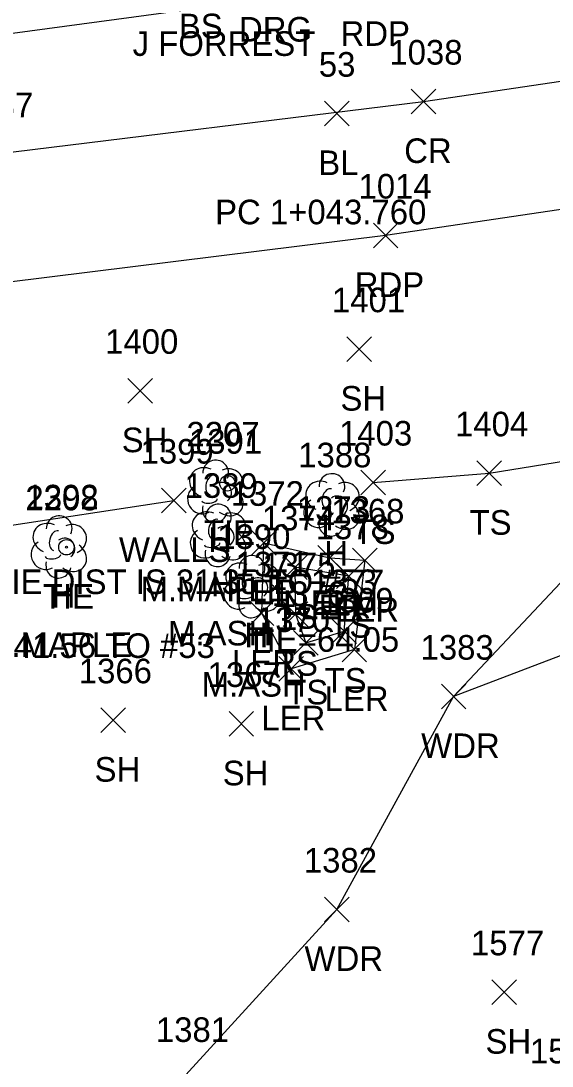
# Model space of a CAD drawing. Extents: x 1526508 to 1531550, y 369926 to 373082.
# Drawn here: x 1530976.9 to 1531020.1, y 370058.1 to 370143.1 of the extents above; entities that cross this region are included whole.
import ezdxf

# ---------------------------------------------------------------- set-up
doc = ezdxf.new("R2010")
doc.units = 0
for name, color, linetype in [('C_A', 7, 'Continuous'), ('C_C', 7, 'Continuous'), ('C_I', 7, 'Continuous'), ('C_TIC', 7, 'Continuous'), ('CBP', 7, 'Continuous'), ('L_A', 7, 'Continuous'), ('L_C', 7, 'Continuous'), ('L_I', 7, 'Continuous'), ('L_TIC', 7, 'Continuous'), ('LARO', 7, 'Continuous'), ('LAWA', 7, 'Continuous'), ('LELB', 7, 'Continuous'), ('LTD', 7, 'Continuous'), ('LWS', 7, 'Continuous'), ('P_A', 7, 'Continuous'), ('P_I', 7, 'Continuous'), ('P_TIC', 7, 'Continuous'), ('PET', 7, 'Continuous'), ('PRC', 7, 'Continuous'), ('R_A', 7, 'Continuous')]:
    doc.layers.add(name, color=color, linetype=linetype)

msp = doc.modelspace()

# ---------------------------------------------------------------- linework, layer by layer
at = {"layer": 'C_TIC'}
for points in [[(1531001.631, 370134.575), (1531003.631, 370136.575)], [(1531003.631, 370134.575), (1531001.631, 370136.575)]]:
    msp.add_lwpolyline(points, dxfattribs=at)
at = {"layer": 'CBP'}
for centre, radius in [((1530993.737, 370105.51), 0.625), ((1530993.737, 370105.51), 0.0833), ((1530980.642, 370100.315), 0.625), ((1530980.642, 370100.315), 0.0833)]:
    msp.add_circle(centre, radius, dxfattribs=at)
at = {"layer": 'L_TIC'}
for points in [[(1531003.438, 370115.426), (1531005.438, 370117.426)], [(1531005.438, 370115.426), (1531003.438, 370117.426)], [(1530985.649, 370112.044), (1530987.649, 370114.044)], [(1530987.649, 370112.044), (1530985.649, 370114.044)], [(1531014.011, 370105.334), (1531016.011, 370107.334)], [(1531016.011, 370105.334), (1531014.011, 370107.334)], [(1531004.583, 370104.584), (1531006.583, 370106.584)], [(1531006.583, 370104.584), (1531004.583, 370106.584)], [(1530988.373, 370103.119), (1530990.373, 370105.119)], [(1530990.373, 370103.119), (1530988.373, 370105.119)], [(1530995.695, 370099.685), (1530997.695, 370101.685)], [(1530997.695, 370099.685), (1530995.695, 370101.685)], [(1531001.073, 370098.469), (1531003.073, 370100.469)], [(1531003.073, 370098.469), (1531001.073, 370100.469)], [(1531003.914, 370098.255), (1531005.914, 370100.255)], [(1531005.914, 370098.255), (1531003.914, 370100.255)], [(1530998.226, 370097.686), (1531000.226, 370099.686)], [(1531000.226, 370097.686), (1530998.226, 370099.686)], [(1531002.604, 370096.968), (1531004.604, 370098.968)], [(1531004.604, 370096.968), (1531002.604, 370098.968)], [(1530995.521, 370093.953), (1530997.521, 370095.953)], [(1530997.521, 370093.953), (1530995.521, 370095.953)], [(1530998.264, 370093.874), (1531000.264, 370095.874)], [(1531000.264, 370093.874), (1530998.264, 370095.874)], [(1531002.222, 370092.494), (1531004.222, 370094.494)], [(1531004.222, 370092.494), (1531002.222, 370094.494)], [(1530999.105, 370091.539), (1531001.105, 370093.539)], [(1531001.105, 370091.539), (1530999.105, 370093.539)], [(1531003.055, 370091.009), (1531005.055, 370093.009)], [(1531005.055, 370091.009), (1531003.055, 370093.009)], [(1530997.909, 370089.427), (1530999.909, 370091.427)], [(1530999.909, 370089.427), (1530997.909, 370091.427)], [(1531011.129, 370087.176), (1531013.129, 370089.176)], [(1531013.129, 370087.176), (1531011.129, 370089.176)], [(1530983.443, 370085.256), (1530985.443, 370087.256)], [(1530985.443, 370085.256), (1530983.443, 370087.256)], [(1530993.867, 370084.959), (1530995.867, 370086.959)], [(1530995.867, 370084.959), (1530993.867, 370086.959)], [(1531001.64, 370069.867), (1531003.64, 370071.867)], [(1531003.64, 370069.867), (1531001.64, 370071.867)], [(1531015.232, 370063.138), (1531017.232, 370065.138)], [(1531017.232, 370063.138), (1531015.232, 370065.138)]]:
    msp.add_lwpolyline(points, dxfattribs=at)
at = {"layer": 'LARO'}
for points in [[(1531004.914, 370099.255), (1531004.055, 370092.009), (1530998.909, 370090.427), (1530996.521, 370094.953), (1530996.695, 370100.685), (1531002.073, 370099.469)], [(1531002.073, 370099.469), (1531004.914, 370099.255)]]:
    msp.add_lwpolyline(points, dxfattribs=at)
at = {"layer": 'LAWA'}
msp.add_lwpolyline([(1530968.161, 370037.392), (1530979.881, 370048.994), (1530990.042, 370057.094), (1531002.64, 370070.867), (1531012.129, 370088.176), (1531024.743, 370101.609), (1531031.255, 370108.889), (1531038.675, 370107.681), (1531051.109, 370105.813), (1531063.824, 370101.61), (1531080.52, 370097.978), (1531114.388, 370088.681)], dxfattribs=at)
at = {"layer": 'LELB'}
for points in [[(1531005.583, 370105.584), (1531015.011, 370106.334), (1531028.597, 370108.539)], [(1530999.226, 370098.686), (1530999.264, 370094.874), (1531000.105, 370092.539), (1531003.222, 370093.494), (1531003.604, 370097.968)], [(1531003.604, 370097.968), (1530999.226, 370098.686)], [(1531027.964, 370094.218), (1531012.129, 370088.176)]]:
    msp.add_lwpolyline(points, dxfattribs=at)
at = {"layer": 'LTD'}
for p, q in [((1530992.734, 370104.923), (1530992.734, 370104.923)), ((1530992.734, 370104.923), (1530992.734, 370104.923)), ((1531002.184, 370103.817), (1531002.184, 370103.817)), ((1531002.184, 370103.817), (1531002.184, 370103.817)), ((1530992.955, 370101.333), (1530992.955, 370101.333)), ((1530992.955, 370101.333), (1530992.955, 370101.333)), ((1530980.008, 370100.394), (1530980.008, 370100.394)), ((1530980.008, 370100.394), (1530980.008, 370100.394)), ((1530995.685, 370097.173), (1530995.685, 370097.173)), ((1530995.685, 370097.173), (1530995.685, 370097.173))]:
    msp.add_line(p, q, dxfattribs=at)
for centre in [(1530992.781, 370106.357), (1531002.231, 370105.251), (1530993.002, 370102.767), (1530980.055, 370101.828), (1530995.732, 370098.607)]:
    msp.add_arc(centre, 1.047, 335.52715, 180.95627, dxfattribs=at)
for centre, major_axis, ratio, start_param, end_param in [((1530991.942, 370105.59), (1.21, -0.512), 0.895232, 1.570796, 4.712389), ((1530993.776, 370105.507), (-1.141, -0.483), 0.949671, 1.570796, 4.712389), ((1530992.526, 370105.382), (-0.208, -0.792), 0.645439, 3.141593, 6.283185), ((1530991.651, 370104.215), (0.584, -1.042), 0.959034, 3.141593, 6.283185), ((1530993.234, 370104.757), (-0.5, 0.667), 0.989748, 3.141593, 6.283185), ((1531001.392, 370104.484), (1.21, -0.512), 0.895232, 1.570796, 4.712389), ((1531001.976, 370104.276), (-0.208, -0.792), 0.645439, 3.141593, 6.283185), ((1531003.226, 370104.401), (-1.141, -0.483), 0.949671, 1.570796, 4.712389), ((1530992.276, 370104.173), (-0.625, -0.083), 0.423636, 0, 3.141593), ((1530993.734, 370104.09), (-1.09, 0.792), 0.841452, 1.570796, 4.712389), ((1531002.684, 370103.651), (-0.5, 0.667), 0.989748, 3.141593, 6.283185), ((1530992.163, 370101.999), (1.21, -0.512), 0.895232, 1.570796, 4.712389), ((1530992.734, 370103.423), (0.265, 1.061), 0.942809, 1.570796, 4.712389), ((1531001.101, 370103.109), (0.584, -1.042), 0.959034, 3.141593, 6.283185), ((1531003.184, 370102.984), (-1.09, 0.792), 0.841452, 1.570796, 4.712389), ((1530992.746, 370101.791), (-0.208, -0.792), 0.645439, 3.141593, 6.283185), ((1530993.996, 370101.916), (-1.141, -0.483), 0.949671, 1.570796, 4.712389), ((1531002.184, 370102.317), (0.265, 1.061), 0.942809, 1.570796, 4.712389), ((1531001.726, 370103.067), (-0.625, -0.083), 0.423636, 0, 3.141593), ((1530979.216, 370101.06), (1.21, -0.512), 0.895232, 1.570796, 4.712389), ((1530979.8, 370100.852), (-0.208, -0.792), 0.645439, 3.141593, 6.283185), ((1530981.05, 370100.977), (-1.141, -0.483), 0.949671, 1.570796, 4.712389), ((1530991.872, 370100.624), (0.584, -1.042), 0.959034, 3.141593, 6.283185), ((1530993.455, 370101.166), (-0.5, 0.667), 0.989748, 3.141593, 6.283185), ((1530980.508, 370100.227), (-0.5, 0.667), 0.989748, 3.141593, 6.283185), ((1530993.955, 370100.5), (-1.09, 0.792), 0.841452, 1.570796, 4.712389), ((1530978.925, 370099.685), (0.584, -1.042), 0.959034, 3.141593, 6.283185), ((1530981.008, 370099.561), (-1.09, 0.792), 0.841452, 1.570796, 4.712389), ((1530992.955, 370099.833), (0.265, 1.061), 0.942809, 1.570796, 4.712389), ((1530992.497, 370100.583), (-0.625, -0.083), 0.423636, 0, 3.141593), ((1530980.008, 370098.894), (0.265, 1.061), 0.942809, 1.570796, 4.712389), ((1530979.55, 370099.644), (-0.625, -0.083), 0.423636, 0, 3.141593), ((1530994.893, 370097.839), (1.21, -0.512), 0.895232, 1.570796, 4.712389), ((1530995.477, 370097.631), (-0.208, -0.792), 0.645439, 3.141593, 6.283185), ((1530996.727, 370097.756), (-1.141, -0.483), 0.949671, 1.570796, 4.712389), ((1530994.602, 370096.464), (0.584, -1.042), 0.959034, 3.141593, 6.283185), ((1530996.185, 370097.006), (-0.5, 0.667), 0.989748, 3.141593, 6.283185), ((1530996.685, 370096.34), (-1.09, 0.792), 0.841452, 1.570796, 4.712389), ((1530995.685, 370095.673), (0.265, 1.061), 0.942809, 1.570796, 4.712389), ((1530995.227, 370096.423), (-0.625, -0.083), 0.423636, 0, 3.141593)]:
    msp.add_ellipse(centre, major_axis=major_axis, ratio=ratio, start_param=start_param, end_param=end_param, dxfattribs=at)
at = {"layer": 'LWS'}
msp.add_lwpolyline([(1530960.132, 370099.667), (1530989.373, 370104.119)], dxfattribs=at)
at = {"layer": 'P_TIC'}
for points in [[(1531008.674, 370135.559), (1531010.674, 370137.559)], [(1531010.674, 370135.559), (1531008.674, 370137.559)], [(1531005.599, 370124.669), (1531007.599, 370126.669)], [(1531007.599, 370124.669), (1531005.599, 370126.669)]]:
    msp.add_lwpolyline(points, dxfattribs=at)
at = {"layer": 'PET'}
for points in [[(1530659.858, 369987.59), (1530689.684, 370004.875), (1530725.765, 370025.628), (1530760.951, 370046.594), (1530789.352, 370063.64), (1530821.517, 370083.594), (1530847.466, 370098.657), (1530877.566, 370115.247), (1530907.835, 370128.264), (1530938.814, 370136.759), (1530967.766, 370140.971), (1531005.443, 370146.083), (1531034.992, 370150.932)], [(1531038.439, 370130.381), (1531006.599, 370125.669), (1530965.469, 370120.559), (1530935.626, 370115.811), (1530906.909, 370106.244), (1530877.457, 370092.886), (1530855.502, 370080.74), (1530824.981, 370062.428), (1530800.479, 370048.152), (1530769.959, 370030.14), (1530741.096, 370012.789), (1530710.763, 369994.526), (1530684.029, 369978.659), (1530669.597, 369970.091)]]:
    msp.add_lwpolyline(points, dxfattribs=at)
at = {"layer": 'PRC'}
msp.add_lwpolyline([(1530664.429, 369978.533), (1530688.651, 369992.904), (1530715.759, 370008.787), (1530744.405, 370025.809), (1530774.386, 370044.325), (1530799.133, 370059.29), (1530828.468, 370076.59), (1530863.719, 370096.733), (1530899.644, 370113.889), (1530935.777, 370125.965), (1530974.766, 370132.269), (1531009.674, 370136.559), (1531036.217, 370140.477)], dxfattribs=at)

# ---------------------------------------------------------------- texts
at = {"layer": 'C_A'}
for s, p in [('BL', (1531001.119, 370130.575)), ('TIE', (1530991.816, 370100.51)), ('TIE', (1530978.721, 370095.315))]:
    msp.add_text(s, height=2, dxfattribs=at).set_placement(p)
at = {"layer": 'C_C'}
for s, p in [('PC 1+043.760', (1530992.733, 370126.575)), ('TIE DIST IS 31.35 TO #53', (1530974.54, 370096.51)), ('TIE DIST IS 41.56 TO #53', (1530961.351, 370091.315))]:
    msp.add_text(s, height=2, dxfattribs=at).set_placement(p)
at = {"layer": 'C_I'}
for s, p in [('53', (1531001.166, 370138.575)), ('2207', (1530990.398, 370108.51)), ('2208', (1530977.304, 370103.315))]:
    msp.add_text(s, height=2, dxfattribs=at).set_placement(p)
at = {"layer": 'L_A'}
for s, p in [('BS', (1530989.782, 370141.698)), ('SH', (1531002.926, 370111.426)), ('SH', (1530985.138, 370108.044)), ('TS', (1531013.421, 370101.334)), ('TS', (1531003.993, 370100.584)), ('H', (1530992.167, 370099.923)), ('WALLS', (1530984.917, 370099.119)), ('H', (1531001.617, 370098.817)), ('H', (1530992.388, 370096.333)), ('LER', (1530994.277, 370095.685)), ('H', (1530979.441, 370095.394)), ('TS', (1530997.635, 370093.686)), ('LER', (1530999.656, 370094.469)), ('LER', (1531002.497, 370094.255)), ('TS', (1531002.013, 370092.968)), ('H', (1530995.118, 370092.173)), ('LER', (1530994.104, 370089.953)), ('TS', (1530997.673, 370089.874)), ('TS', (1531001.632, 370088.494)), ('TS', (1530998.514, 370087.539)), ('LER', (1531001.637, 370087.009)), ('LER', (1530996.492, 370085.427)), ('WDR', (1531009.491, 370083.176)), ('SH', (1530982.931, 370081.256)), ('SH', (1530993.355, 370080.959)), ('WDR', (1531000.003, 370065.867)), ('SH', (1531014.72, 370059.138))]:
    msp.add_text(s, height=2, dxfattribs=at).set_placement(p)
at = {"layer": 'L_C'}
for s, p in [('J FORREST', (1530986.023, 370140.267)), ('M.MAPLE', (1530986.671, 370095.923)), ('L.ELM', (1530998.263, 370094.817)), ('M.ASH', (1530988.908, 370092.333)), ('M.MAPLE', (1530973.945, 370091.394)), ('TIE=64.05', (1530995.287, 370091.817)), ('M.ASH', (1530991.638, 370088.173))]:
    msp.add_text(s, height=2, dxfattribs=at).set_placement(p)
at = {"layer": 'L_I'}
for s, p in [('1401', (1531002.233, 370119.426)), ('1400', (1530983.791, 370116.044)), ('1404', (1531012.24, 370109.334)), ('1403', (1531002.811, 370108.584)), ('1391', (1530990.608, 370107.923)), ('1399', (1530986.673, 370107.119)), ('1388', (1530999.491, 370106.817)), ('1389', (1530990.254, 370104.333)), ('1392', (1530977.315, 370103.394)), ('1372', (1530994.002, 370103.685)), ('1373', (1530999.38, 370102.469)), ('1368', (1531002.174, 370102.255)), ('1374', (1530996.533, 370101.686)), ('1378', (1531000.911, 370100.968)), ('1390', (1530992.906, 370100.173)), ('1371', (1530994.395, 370097.953)), ('1375', (1530996.571, 370097.874)), ('1377', (1531000.529, 370096.494)), ('1376', (1530997.357, 370095.539)), ('1369', (1531001.307, 370095.009)), ('1370', (1530996.13, 370093.427)), ('1383', (1531009.436, 370091.176)), ('1366', (1530981.648, 370089.256)), ('1367', (1530992.126, 370088.959)), ('1382', (1530999.947, 370073.867)), ('1577', (1531013.539, 370067.138)), ('1381', (1530987.916, 370060.094)), ('1594', (1531018.329, 370058.353))]:
    msp.add_text(s, height=2, dxfattribs=at).set_placement(p)
at = {"layer": 'P_A'}
for s, p in [('RDP', (1531002.931, 370141.083)), ('CR', (1531008.107, 370131.559)), ('RDP', (1531004.087, 370120.669))]:
    msp.add_text(s, height=2, dxfattribs=at).set_placement(p)
at = {"layer": 'P_I'}
for s, p in [('1038', (1531006.902, 370139.559)), ('1037', (1530971.994, 370135.269)), ('1014', (1531004.394, 370128.669))]:
    msp.add_text(s, height=2, dxfattribs=at).set_placement(p)
at = {"layer": 'R_A'}
msp.add_text('DRG', height=2, dxfattribs=at).set_placement((1530994.675, 370141.43))

doc.saveas('drawing.dxf')
